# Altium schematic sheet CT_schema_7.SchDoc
size 278 x 170 mm
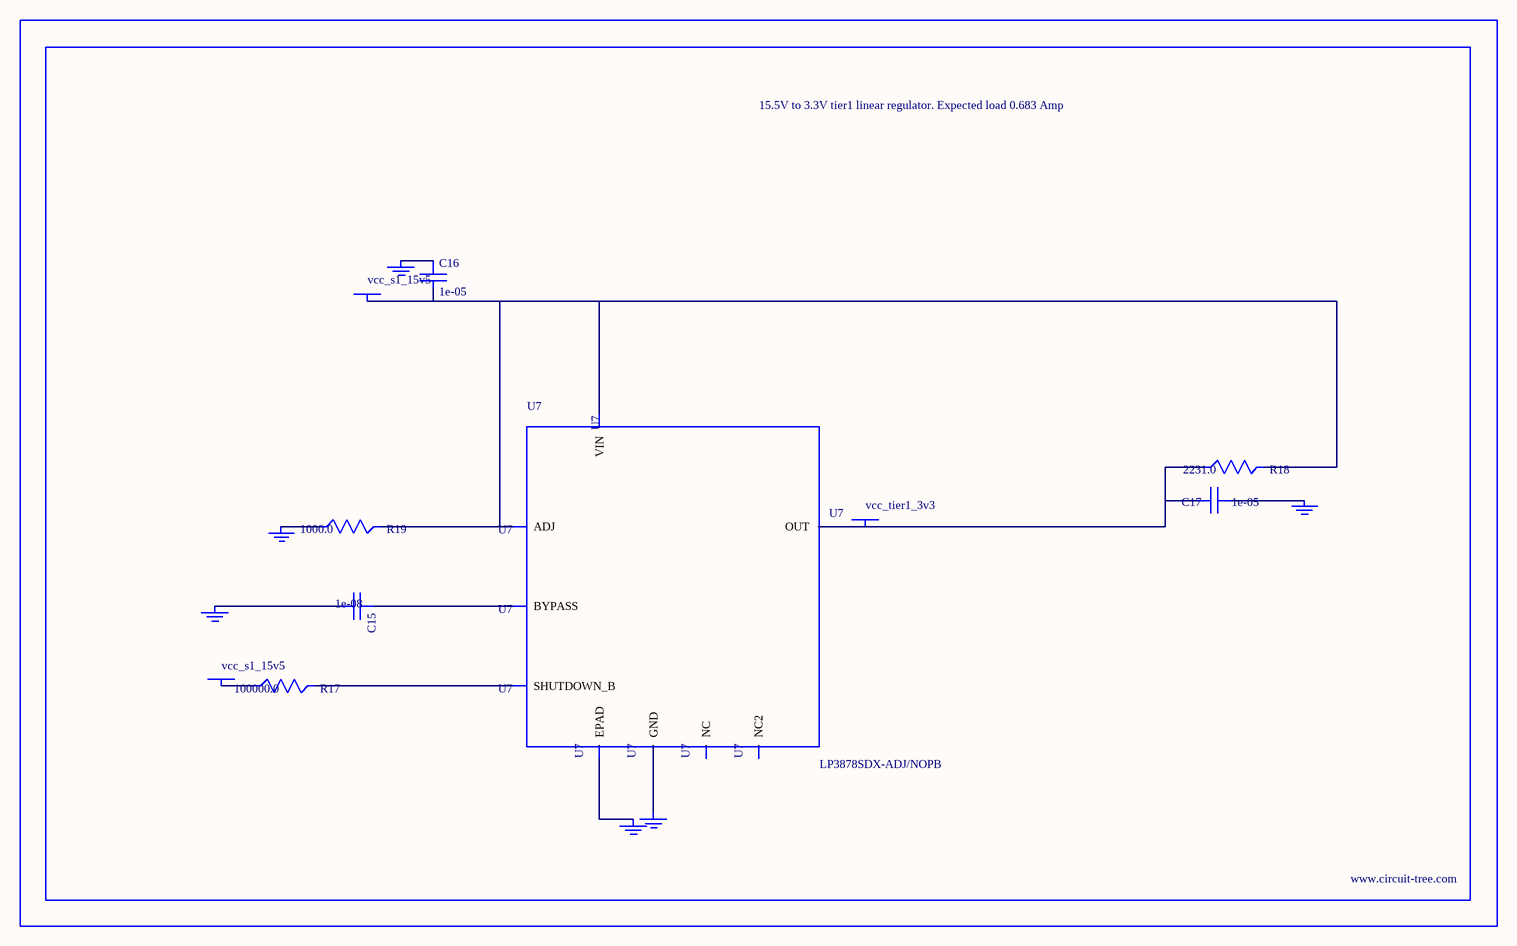
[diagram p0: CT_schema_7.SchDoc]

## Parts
BORDER6  (no value)
C15  1e-08  [C0402]
C16  1e-05  [C1210]
C17  1e-05  [C1210]
GND_INSTANCE_6_0  (no value)
GND_INSTANCE_6_1  (no value)
GND_INSTANCE_6_2  (no value)
GND_INSTANCE_6_3  (no value)
GND_INSTANCE_6_4  (no value)
GND_INSTANCE_6_5  (no value)
POWER_INSTANCE_6_0  vcc_s1_15v5
POWER_INSTANCE_6_1  vcc_s1_15v5
POWER_INSTANCE_6_2  vcc_tier1_3v3
R17  100000.0  [R0603]
R18  2231.0  [R0603]
R19  1000.0  [R0603]
U7  LP3878SDX-ADJ/NOPB  [WSON-8]

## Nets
NetC15_1: C15.1 U7.1(BYPASS)
NetC15_2: C15.2 GND_INSTANCE_6_0.0(GND)
NetC16_1: C16.1 GND_INSTANCE_6_1.0(GND)
NetC16_2: C16.2 POWER_INSTANCE_6_0.0(PWR) R18.2 R19.2 U7.4(VIN) U7.6(ADJ)
NetC17_1: C17.1 GND_INSTANCE_6_2.0(GND)
NetC17_2: C17.2 POWER_INSTANCE_6_2.0(PWR) R18.1 U7.5(OUT)
NetGND_INSTANCE_6_3_0: GND_INSTANCE_6_3.0(GND) R19.1
NetGND_INSTANCE_6_4_0: GND_INSTANCE_6_4.0(GND) U7.PAD(EPAD)
NetGND_INSTANCE_6_5_0: GND_INSTANCE_6_5.0(GND) U7.3(GND)
NetPOWER_INSTANCE_6_1_0: POWER_INSTANCE_6_1.0(PWR) R17.1
NetR17_2: R17.2 U7.8(SHUTDOWN_B)

Not connected (* = marked no-connect by the designer): U7 2(NC) 7(NC2)

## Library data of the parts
BORDER6 = BORDER_PAGE6
C15 = C0402C103K3RAC
C16 = C1210C106K5PACTU
C17 = GRM32DR61E106MA12L
GND_INSTANCE_6_0-GND_INSTANCE_6_5 = GND
POWER_INSTANCE_6_0-POWER_INSTANCE_6_2 = PWR
R17 = RC0603JR-07100KL
R18 = R18
R19 = RC0603JR-071KL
